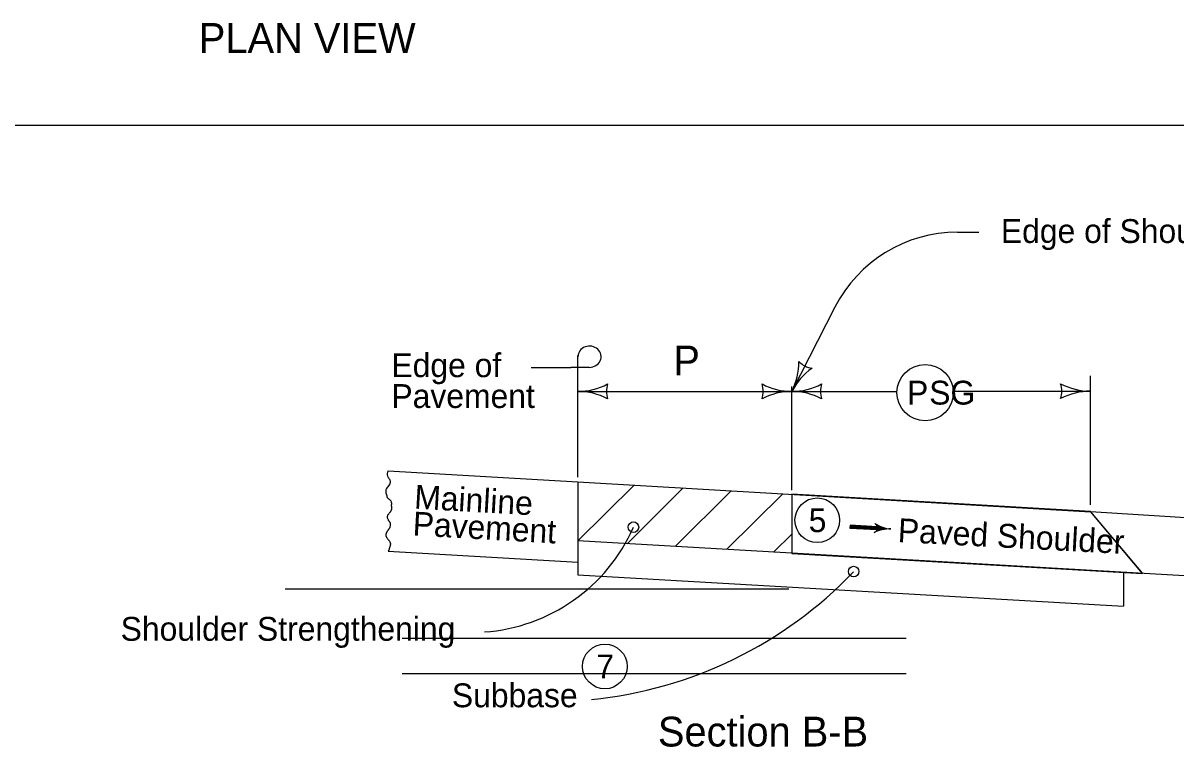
# Model space of a CAD drawing. Extents: x 8045 to 81668, y 6217 to 16762.
# Drawn here: x 11036 to 11810, y 8939 to 9425 of the extents above; entities that cross this region are included whole.
import ezdxf

# ---------------------------------------------------------------- set-up
doc = ezdxf.new("R2010")
doc.units = 0
for name, color, linetype in [('dsnStdDetailExtension', 7, 'Continuous'), ('dsnStdLabel', 7, 'Continuous'), ('dsnStdLineWork', 7, 'Continuous'), ('dsnStdNote', 7, 'Continuous'), ('dsnStdPattern', 7, 'Continuous'), ('Level 4', 7, 'Continuous'), ('Level 8', 7, 'Continuous'), ('TextBlockOut', 7, 'Continuous')]:
    doc.layers.add(name, color=color, linetype=linetype)

msp = doc.modelspace()

# ---------------------------------------------------------------- linework, layer by layer
at = {"layer": 'dsnStdDetailExtension'}
for centre in [(11445.98, 9086.76), (11445.98, 9086.76), (11593.92, 9056.91), (11593.92, 9056.91)]:
    msp.add_circle(centre, 3.54, dxfattribs=at)
at = {"layer": 'dsnStdLabel'}
for p, q in [((11281.22, 9124.58), (11408.68, 9117.17)), ((11408.68, 9117.17), (11408.68, 9063.16)), ((11408.68, 9117.17), (11752.97, 9097.15)), ((11552.45, 9108.8), (11552.45, 9069)), ((11752.52, 9097.34), (11752.52, 9097.34)), ((11752.97, 9097.15), (11788.01, 9055.7)), ((11752.98, 9097.23), (11887.73, 9088.85)), ((11984.79, 9044.35), (11408.68, 9077.58)), ((11281.25, 9070.57), (11408.68, 9063.16)), ((11775.21, 9070.85), (11775.21, 9070.85)), ((11408.68, 9063.16), (11408.68, 9054.74)), ((11408.68, 9054.74), (11775.21, 9033.6)), ((11775.21, 9056.43), (11775.21, 9033.6)), ((11211.96, 9045.23), (11550.46, 9045.23)), ((11290.63, 9012.25), (11629.13, 9012.25)), ((11290.63, 8988.58), (11629.13, 8988.58))]:
    msp.add_line(p, q, dxfattribs=at)
for points in [[(11281.22, 9124.58), (11280.71, 9120.98), (11281.76, 9119.47), (11282.62, 9117.18), (11282.01, 9115.12), (11280.11, 9112.74), (11279.59, 9110.84), (11280.11, 9108.54), (11280.98, 9106.17), (11282.01, 9105.45), (11283.4, 9102.92), (11283.39, 9102.08)], [(11281.43, 9084.97), (11281.64, 9085.22), (11281.84, 9085.48), (11282.19, 9086.04), (11282.47, 9086.63), (11282.59, 9086.93), (11282.69, 9087.25), (11282.82, 9087.87), (11282.87, 9088.49), (11282.82, 9089.08), (11282.76, 9089.35), (11282.72, 9089.49), (11282.68, 9089.62), (11282.47, 9090), (11282.19, 9090.36), (11281.89, 9090.73), (11281.64, 9091.12), (11281.5, 9091.41), (11281.36, 9091.69), (11281.1, 9092.26), (11280.9, 9092.83), (11280.83, 9093.12), (11280.77, 9093.42), (11280.76, 9093.55), (11280.76, 9093.67), (11280.91, 9094.45), (11281.12, 9094.97), (11281.38, 9095.48), (11281.82, 9096.12), (11282.34, 9096.66), (11282.86, 9097.21), (11283.09, 9097.51), (11283.29, 9097.86), (11283.49, 9098.33), (11283.65, 9098.8), (11283.75, 9099.28), (11283.78, 9099.52), (11283.8, 9099.64), (11283.81, 9099.76), (11283.76, 9100.26), (11283.61, 9100.78), (11283.56, 9100.91), (11283.5, 9101.03), (11283.45, 9101.16), (11283.43, 9101.29), (11283.39, 9102.08)], [(11281.43, 9084.97), (11281.21, 9084.73), (11280.97, 9084.5), (11280.73, 9084.26), (11280.55, 9083.99), (11280.41, 9083.7), (11280.27, 9083.42), (11280.01, 9082.85), (11279.9, 9082.56), (11279.8, 9082.28), (11279.73, 9081.98), (11279.7, 9081.84), (11279.68, 9081.69), (11279.69, 9081.17), (11279.82, 9080.66), (11280.03, 9080.14), (11280.29, 9079.63), (11280.73, 9078.99), (11281.25, 9078.45), (11281.77, 9077.9), (11282, 9077.6), (11282.2, 9077.26), (11282.6, 9076.31), (11282.71, 9075.83), (11282.72, 9075.36), (11282.68, 9075.07), (11282.63, 9074.78), (11282.58, 9074.49), (11282.51, 9074.21), (11282.2, 9073.06), (11282.02, 9072.45), (11281.82, 9071.85), (11281.6, 9071.26), (11281.47, 9070.97), (11281.33, 9070.68), (11281.25, 9070.57)]]:
    msp.add_spline(points, degree=3, dxfattribs=at)
at = {"layer": 'dsnStdLineWork'}
for p, q in [((11663.64, 9284.83), (11677.95, 9284.83)), ((11581.34, 9234.46), (11552.44, 9177.9)), ((11408.68, 9181.22), (11408.68, 9202.08)), ((11377.31, 9194.07), (11403.99, 9194.07)), ((11416.49, 9194.07), (11403.99, 9194.07)), ((11752.98, 9101.79), (11752.98, 9188.45)), ((11408.68, 9120.31), (11408.68, 9181.22)), ((11408.68, 9177.9), (11623, 9177.9)), ((11552.44, 9111.66), (11552.44, 9181.22)), ((11660.83, 9178.05), (11752.98, 9178.05)), ((11408.68, 9077.57), (11446.48, 9114.97)), ((11441.72, 9075.66), (11479.51, 9113.07)), ((11473.96, 9073.81), (11511.75, 9111.21)), ((11508.57, 9071.81), (11546.36, 9109.21)), ((11609.71, 9086.06), (11591.5, 9087.11)), ((11609.61, 9085.12), (11609.61, 9085.12)), ((11609.72, 9087.07), (11609.72, 9087.07)), ((11540.19, 9069.99), (11552.45, 9082.12))]:
    msp.add_line(p, q, dxfattribs=at)
for points in [[(11609.74, 9087), (11591.57, 9088.05), (11591.44, 9086.17), (11609.61, 9085.12), (11609.66, 9086.73), (11591.79, 9087.83), (11591.73, 9086.33), (11609.22, 9085.38), (11609.35, 9086.5), (11592.02, 9087.56), (11592, 9086.56), (11609.01, 9085.58), (11609.1, 9086.29), (11592.21, 9087.34), (11592.2, 9086.78), (11608.8, 9085.84)], [(11609.33, 9088.26), (11610.03, 9087.09), (11610, 9085.44), (11609.24, 9084.05), (11612, 9084.91), (11615.19, 9085.56), (11616.09, 9085.7), (11613.85, 9086.24), (11610.62, 9087.47), (11609.68, 9088.01), (11609.8, 9084.49), (11614.75, 9085.71), (11610.11, 9087.29), (11610.12, 9084.87), (11613.52, 9085.8), (11610.52, 9086.66), (11610.29, 9085.28), (11612.45, 9085.78), (11610.86, 9086.29), (11610.72, 9085.63), (11611.51, 9085.79)]]:
    msp.add_lwpolyline(points, dxfattribs=at)
msp.add_circle((11641.92, 9177.08), 18.93, dxfattribs=at)
for centre, radius, start, end in [((11663.64, 9192.4), 92.43, 90, 152.9341), ((11514.59, 9197.24), 42.5, 332.9341, 1.00659), ((11590.28, 9158.56), 42.5, 124.86161, 152.9341), ((11568.65, 9209.63), 16.42, 225.20075, 260.66745), ((11408.68, 9220.4), 42.5, 270, 298.07249), ((11408.68, 9135.4), 42.5, 61.92751, 90), ((11444.32, 9177.9), 16.42, 162.26665, 197.73335), ((11516.8, 9177.9), 16.42, 342.26665, 17.73335), ((11552.44, 9220.4), 42.5, 241.92751, 270), ((11552.44, 9135.4), 42.5, 90, 118.07249), ((11552.44, 9220.4), 42.5, 270, 298.07249), ((11552.44, 9135.4), 42.5, 61.92751, 90), ((11588.07, 9177.9), 16.42, 162.26665, 197.73335), ((11717.34, 9178.05), 16.42, 342.26665, 17.73335), ((11752.98, 9220.55), 42.5, 241.92751, 270), ((11752.98, 9135.55), 42.5, 90, 118.07249), ((11337.43, 9134.93), 118.88, 274.08506, 336.06992), ((11389.97, 9251.67), 282.03, 275.67842, 316.28441)]:
    msp.add_arc(centre, radius, start, end, dxfattribs=at)
for centre, major_axis, start_param, end_param in [((11416.49, 9201.2), (-7.81, 0), 1.570796, 6.283185), ((11605.94, 9086.28), (3.88, 0), 5.202895, 7.237436), ((11618.21, 9065.28), (22.17, 0), 1.537172, 2.061295), ((11621, 9105.7), (-22.17, 0), 0.954258, 1.478381)]:
    msp.add_ellipse(centre, major_axis=major_axis, ratio=0.913811, start_param=start_param, end_param=end_param, dxfattribs=at)
at = {"layer": 'dsnStdPattern'}
for p, q in [((11552.49, 9108.81), (11552.45, 9069)), ((11752.98, 9097.23), (11552.49, 9108.81)), ((11788.01, 9055.7), (11752.98, 9097.23)), ((11552.45, 9069), (11788.01, 9055.7))]:
    msp.add_line(p, q, dxfattribs=at)
at = {"layer": 'Level 4'}
msp.add_line((12307.76, 9356.36), (10152.18, 9356.36), dxfattribs=at)
at = {"layer": 'Level 8'}
for centre in [(11569.5, 9091.41), (11426.79, 8993.21)]:
    msp.add_circle(centre, 15, dxfattribs=at)
at = {"layer": 'TextBlockOut'}
msp.add_circle((11569.5, 9091.41), 15, dxfattribs=at)

# ---------------------------------------------------------------- texts
at = {"layer": 'dsnStdLineWork'}
for s, height, p in [('Edge of Shoulder Strengthening', 16, (11692.84, 9277.59)), ('P', 20, (11472.84, 9188.64)), ('Edge of ', 16, (11283.43, 9187.48)), ('P', 16, (11629.79, 9169.08)), ('SG', 16, (11644.71, 9169.08)), ('Pavement', 16, (11283.43, 9166.78)), ('Shoulder Strengthening', 16, (11101.54, 9010.47)), ('Subbase', 16, (11324.05, 8965.83)), ('Section B-B', 20, (11462.44, 8939.46))]:
    msp.add_text(s, height=height, dxfattribs=at).set_placement(p)
for s, rotation, p in [('Mainline', 356.73462, (11298.44, 9099.24)), ('Pavement', 356.73462, (11297.41, 9081.27)), ('Paved Shoulder ', 356.98301, (11623.32, 9076.79))]:
    msp.add_text(s, height=16, rotation=rotation, dxfattribs=at).set_placement(p)
at = {"layer": 'dsnStdNote'}
msp.add_text('PLAN VIEW', height=20, dxfattribs=at).set_placement((11154.04, 9405.26))
msp.add_text('PLAN VIEW', height=20, dxfattribs=at).set_placement((11154.04, 9405.26))
at = {"layer": 'Level 8'}
for s, p in [('5', (11563.73, 9083.41)), ('7', (11421.08, 8985.21))]:
    msp.add_text(s, height=16, dxfattribs=at).set_placement(p)

doc.saveas('drawing.dxf')
